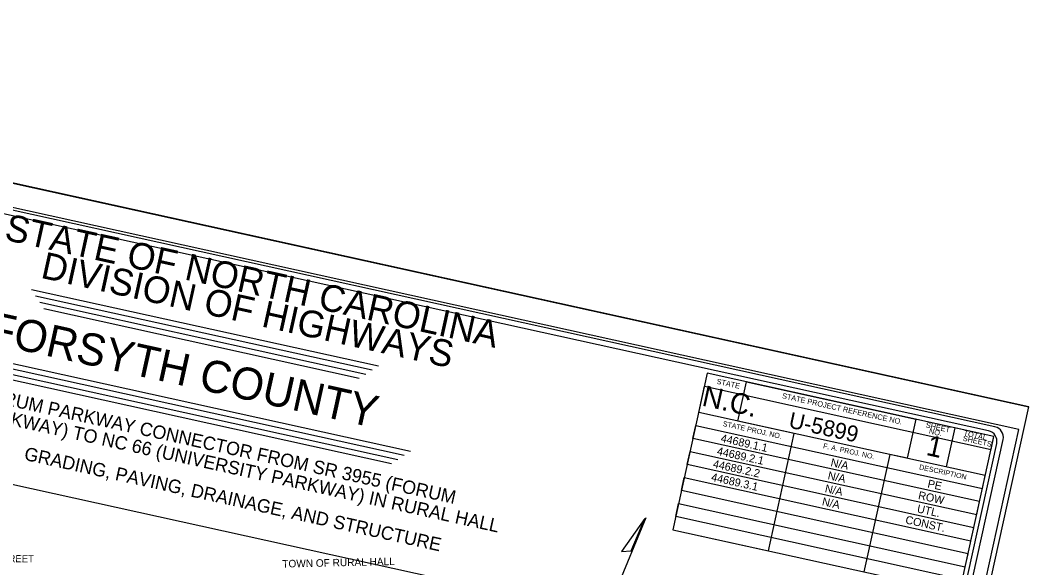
# Model space of a CAD drawing. Extents: x 1609449 to 1623942, y 894240 to 902860.
# Drawn here: x 1618272 to 1623942, y 899782 to 902860 of the extents above; entities that cross this region are included whole.
import ezdxf

# ---------------------------------------------------------------- set-up
doc = ezdxf.new("R2010")
doc.units = 0
for name, color, linetype in [('Prop Horizontal Alignment Station Label', 7, 'Continuous'), ('Scratch_Level_0', 7, 'Continuous'), ('Scratch_Level_1', 7, 'Continuous'), ('Sheet Cutting Line CELL', 7, 'Continuous'), ('Sheet Data Field CELL', 7, 'Continuous'), ('Sheet North Arrow CELL', 7, 'Continuous'), ('Sheet Plot Border Inside CELL', 7, 'Continuous'), ('Sheet Plot Border Outside CELL', 7, 'Continuous'), ('Sheet Title CELL', 7, 'Continuous'), ('Sheet Title Data Points CELL', 7, 'Continuous')]:
    doc.layers.add(name, color=color, linetype=linetype)

msp = doc.modelspace()

# ---------------------------------------------------------------- linework, layer by layer
at = {"layer": 'Scratch_Level_0'}
msp.add_lwpolyline([(1615937.3, 900755.3), (1622890.3, 899223.5), (1622107.1, 895668.6), (1615154.1, 897200.4)], close=True, dxfattribs=at)
at = {"layer": 'Scratch_Level_1'}
msp.add_lwpolyline([(1615937.3, 900755.3), (1622890.3, 899223.5), (1622107.1, 895668.6), (1615154.1, 897200.4)], close=True, dxfattribs=at)
at = {"layer": 'Sheet Cutting Line CELL'}
msp.add_line((1614074.8, 902859.7), (1623942.2, 900685.8), dxfattribs=at)
at = {"layer": 'Sheet North Arrow CELL'}
msp.add_line((1621460.5, 899272.5), (1621791.4, 900064.2), dxfattribs=at)
msp.add_lwpolyline([(1621783, 900059.5), (1621651.9, 899872.8), (1621706.6, 899876.8)], close=True, dxfattribs=at)
at = {"layer": 'Sheet Plot Border Inside CELL'}
msp.add_lwpolyline([(1612759.9, 896529.1), (1622524.8, 894377.7), (1623886.8, 900560.1), (1614122, 902711.4)], close=True, dxfattribs=at)
at = {"layer": 'Sheet Plot Border Outside CELL'}
msp.add_lwpolyline([(1623942.2, 900685.8), (1614074.8, 902859.7), (1612654.8, 896414.4), (1622522.2, 894240.5)], close=True, dxfattribs=at)
at = {"layer": 'Sheet Title CELL'}
for p, q in [((1618335.9, 901346.2), (1620285.6, 900916.7)), ((1618358.7, 901310.5), (1620249.8, 900893.8)), ((1618381.5, 901274.7), (1620214.1, 900871)), ((1618404.4, 901238.9), (1620178.4, 900848.2)), ((1617970.1, 900987), (1620466.2, 900436.9)), ((1617992.9, 900951.2), (1620430.5, 900414.1)), ((1618015.8, 900915.4), (1620394.7, 900391.3)), ((1618038.6, 900879.7), (1620359, 900368.4))]:
    msp.add_line(p, q, dxfattribs=at)
for points in [[(1623751.8, 900574.2), (1615079.6, 902484.8)], [(1623715.9, 900551.3), (1615395.5, 902384.4)], [(1623568.4, 899714.5), (1621957.1, 900069.6), (1621973.2, 900142.7), (1623584.6, 899787.7), (1623600.7, 899861), (1621989.4, 900216), (1622005.5, 900289.3), (1623616.9, 899934.3), (1623633, 900007.5), (1622021.6, 900362.5), (1622037.7, 900435.7), (1623649.1, 900080.8), (1623665.2, 900153.9), (1622053.9, 900508.9), (1622070, 900582.2), (1623681.4, 900227.2), (1623697.5, 900300.5), (1622086.2, 900655.5), (1622118.4, 900802), (1623729.8, 900447), (1623745.9, 900520.2), (1622134.6, 900875.2), (1621940.9, 899996.3), (1622478, 899877.9), (1622623.2, 900537.1), (1622305.9, 900607), (1622354.3, 900826.8), (1623306.5, 900617), (1623258.1, 900397.3), (1623160.2, 900418.9), (1623015, 899759.7)], [(1623552.3, 899641.3), (1623745.9, 900520.2), (1623526.2, 900568.6), (1623477.9, 900348.9)], [(1622467.7, 894467.5), (1623797.4, 900502.7)], [(1622683.7, 895587.2), (1623761.6, 900479.9)], [(1621940.9, 899996.3), (1623552.3, 899641.3)]]:
    msp.add_lwpolyline(points, dxfattribs=at)
for centre in [(1623738.9, 900515.9), (1623703.1, 900493.1)]:
    msp.add_arc(centre, 60, 347.5755, 77.5755, dxfattribs=at)
at = {"layer": 'Sheet Title Data Points CELL'}
msp.add_line((1619336.1, 900443.6), (1619336.1, 900443.6), dxfattribs=at)

# ---------------------------------------------------------------- texts
at = {"layer": 'Prop Horizontal Alignment Station Label'}
for s, height, rotation, p in [('ANGUS STREET', 40, 359.3733, (1617932.7, 899816.7)), ('TOWN OF RURAL HALL', 42.35, 1.3164, (1619745.8, 899783.1))]:
    msp.add_text(s, height=height, rotation=rotation, dxfattribs=at).set_placement(p)
at = {"layer": 'Sheet Data Field CELL'}
for s, height, p in [('FORSYTH COUNTY', 180, (1618080.7, 901048.3)), ('FORUM PARKWAY CONNECTOR FROM SR 3955 (FORUM', 75.001, (1618034.6, 900730.4)), ('PARKWAY) TO NC 66 (UNIVERSITY PARKWAY) IN RURAL HALL', 75.001, (1618012.1, 900628.4)), ('U-5899', 90, (1622587.2, 900570.8)), ('44689.1.1', 45, (1622207.4, 900490.2)), ('GRADING, PAVING, DRAINAGE, AND STRUCTURE', 75.001, (1618289.9, 900389.4)), ('44689.2.1', 45, (1622186, 900418.1)), ('44689.2.2', 45, (1622163.6, 900346.3)), ('N/A', 45, (1622825.2, 900354.1)), ('44689.3.1', 45, (1622153.7, 900271.7)), ('N/A', 45, (1622809, 900280.8)), ('N/A', 45, (1622792.9, 900207.7)), ('PE', 45, (1623369.8, 900234.7)), ('N/A', 45, (1622776.8, 900134.4)), ('ROW', 45, (1623317.2, 900169.5)), ('UTL.', 45, (1623310.8, 900094.2)), ('CONST.', 45, (1623245.2, 900031.8))]:
    msp.add_text(s, height=height, rotation=347.5755, dxfattribs=at).set_placement(p)
at = {"layer": 'Sheet Title CELL'}
for s, height, p in [('STATE OF NORTH CAROLINA', 149.999, (1618177.7, 901626.5)), ('DIVISION OF HIGHWAYS', 149.999, (1618381.8, 901412.6)), ('N.C.', 116.1, (1622099.4, 900694.7)), ('STATE', 30, (1622184.6, 900816.6)), ('STATE PROJECT REFERENCE NO.', 29.999, (1622552.9, 900735.4)), ('STATE PROJ. NO.', 28.8, (1622219.6, 900579.1)), ('SHEET', 30, (1623360.6, 900571.3)), ('1', 116.1, (1623359.8, 900417)), ('NO.', 30, (1623378.5, 900537)), ('SHEETS', 30, (1623568.7, 900496.9)), ('TOTAL', 30, (1623573.2, 900526.6)), ('F. A. PROJ. NO.', 28.8, (1622783.8, 900454.8)), ('DESCRIPTION', 28.8, (1623323.5, 900335.8))]:
    msp.add_text(s, height=height, rotation=347.5755, dxfattribs=at).set_placement(p)

doc.saveas('drawing.dxf')
